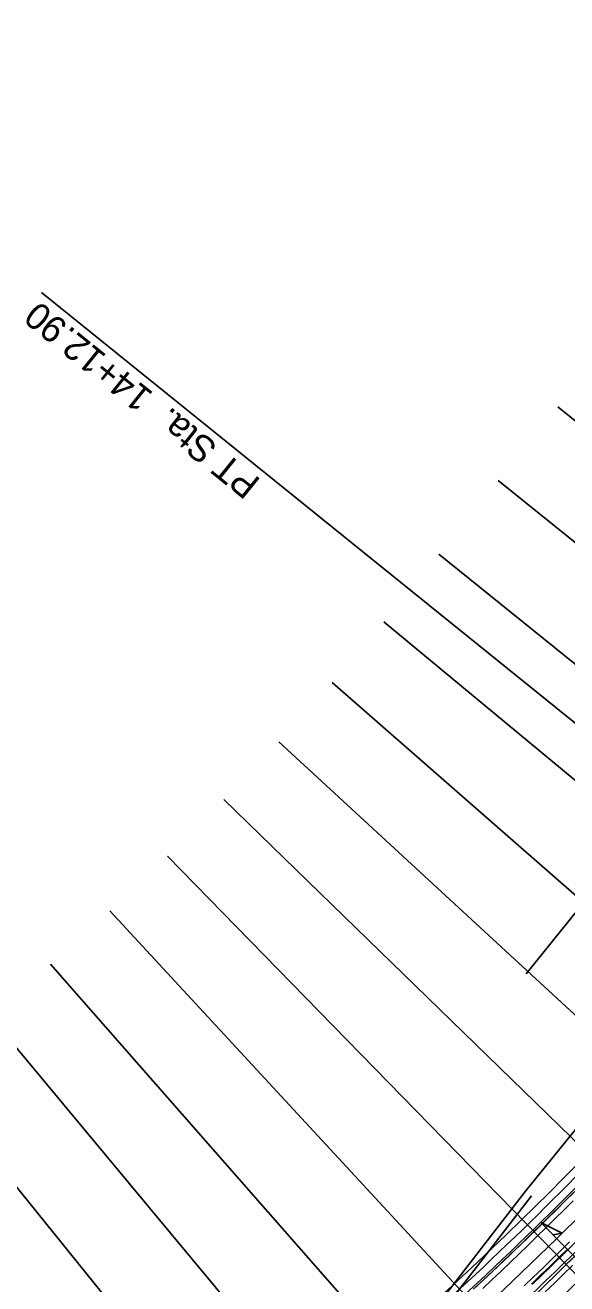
# Model space of a CAD drawing. Extents: x 2293233 to 2294507, y 892788 to 894229.
# Drawn here: x 2293544.7 to 2293687.7, y 893239.9 to 893572.2 of the extents above; entities that cross this region are included whole.
import ezdxf

# ---------------------------------------------------------------- set-up
doc = ezdxf.new("R2010")
doc.units = 0
for name, color, linetype in [('COGO Default Curve', 7, 'Continuous'), ('Prop EOT', 7, 'Continuous'), ('Prop Horizontal Alignment', 7, 'Continuous'), ('Prop Paved Shoulder', 7, 'Continuous'), ('Prop Superelevation  Arrow CELL', 7, 'Continuous'), ('Scratch_Level_0', 7, 'Continuous'), ('Scratch_Level_4', 7, 'Continuous'), ('Scratch_Level_5', 7, 'Continuous')]:
    doc.layers.add(name, color=color, linetype=linetype)

msp = doc.modelspace()

# ---------------------------------------------------------------- linework, layer by layer
at = {"layer": 'COGO Default Curve'}
for points in [[(2294044.74, 893680.7), (2293954.06, 893568.41), (2293770.67, 893341.16), (2293761.43, 893329.77), (2293756.77, 893324.11), (2293752.51, 893318.98), (2293748.22, 893313.88), (2293744.11, 893309.05), (2293739.98, 893304.26), (2293735.81, 893299.49), (2293731.62, 893294.74), (2293727.39, 893290.03), (2293722.91, 893285.09), (2293718.62, 893280.44), (2293714.3, 893275.81), (2293709.95, 893271.21), (2293705.56, 893266.64), (2293701.15, 893262.1), (2293696.71, 893257.59), (2293692.23, 893253.11), (2293687.73, 893248.66), (2293683.19, 893244.24), (2293678.63, 893239.85)], [(2293680.14, 893237.74), (2293686.34, 893243.78), (2293692.26, 893249.64), (2293698.14, 893255.55), (2293703.96, 893261.51), (2293709.74, 893267.51), (2293715.47, 893273.56), (2293720.92, 893279.42), (2293726.55, 893285.56), (2293732.12, 893291.75), (2293737.87, 893298.24), (2293743.8, 893305.01), (2293749.89, 893312.08), (2293756.38, 893319.69), (2293763.26, 893327.84), (2293770.53, 893336.54), (2293778.4, 893346.03), (2293786.88, 893356.32), (2293796.39, 893367.93), (2293808.61, 893382.91), (2293822.69, 893400.24), (2293860.23, 893446.62), (2293932.89, 893536.61), (2294046.75, 893677.72)], [(2293663.1, 893238.53), (2293667.97, 893243.08), (2293672.81, 893247.67), (2293677.62, 893252.29), (2293682.39, 893256.94), (2293687.14, 893261.63), (2293692.08, 893266.58)], [(2293689.56, 893264.05), (2293687.22, 893261.71), (2293684.86, 893259.37), (2293682.5, 893257.05), (2293680.13, 893254.73), (2293677.75, 893252.42), (2293675.37, 893250.11), (2293672.97, 893247.82), (2293670.57, 893245.53), (2293668.16, 893243.26), (2293665.75, 893240.99), (2293663.32, 893238.73)], [(2293689.37, 893261.8), (2293687.02, 893259.45), (2293684.66, 893257.11), (2293682.3, 893254.78), (2293679.92, 893252.46), (2293677.54, 893250.14), (2293675.15, 893247.84), (2293672.75, 893245.54), (2293670.35, 893243.25), (2293667.93, 893240.97), (2293665.51, 893238.7)], [(2293688.46, 893250.98), (2293686.07, 893248.64), (2293683.67, 893246.31), (2293681.26, 893243.99), (2293678.85, 893241.67), (2293676.42, 893239.37)], [(2293687.99, 893249.16), (2293685.6, 893246.82), (2293683.2, 893244.49), (2293680.79, 893242.16), (2293678.37, 893239.85)], [(2293682.27, 893239.81), (2293684.65, 893242.12), (2293687.02, 893244.44), (2293689.38, 893246.77)], [(2293682.03, 893237.81), (2293684.43, 893240.11), (2293686.81, 893242.42), (2293689.19, 893244.74)]]:
    msp.add_lwpolyline(points, dxfattribs=at)
for radius in [944, 956]:
    msp.add_arc((2293023.75, 893925.54), radius, 308.6085, 321.09608, dxfattribs=at)
at = {"layer": 'Prop EOT'}
for radius, start in [(938, 309.40221), (962, 308.6085)]:
    msp.add_arc((2293023.75, 893925.54), radius, start, 321.09608, dxfattribs=at)
at = {"layer": 'Prop Horizontal Alignment'}
for p, q in [((2293761.87, 893329.86), (2293549.03, 893501.62)), ((2293687.08, 893245.48), (2293683.59, 893249.05))]:
    msp.add_line(p, q, dxfattribs=at)
msp.add_arc((2293023.75, 893925.54), 950, 308.6085, 321.09608, dxfattribs=at)
msp.add_arc((2293023.75, 893925.54), 950, 308.6085, 321.09608, dxfattribs=at)
at = {"layer": 'Prop Paved Shoulder'}
for radius, start in [(936, 310.01837), (964, 308.6085)]:
    msp.add_arc((2293023.75, 893925.54), radius, start, 321.09608, dxfattribs=at)
at = {"layer": 'Prop Superelevation  Arrow CELL'}
msp.add_line((2293680.83, 893256.14), (2293697.64, 893239.02), dxfattribs=at)
msp.add_lwpolyline([(2293680.83, 893256.14), (2293686.46, 893253.26), (2293684.07, 893252.84)], close=True, dxfattribs=at)
at = {"layer": 'Scratch_Level_0'}
for p, q in [((2293696.14, 893345.54), (2293676.95, 893321.77)), ((2293678.41, 893263.12), (2293651.3, 893228.13))]:
    msp.add_line(p, q, dxfattribs=at)
at = {"layer": 'Scratch_Level_4'}
for p, q in [((2293685.31, 893471.45), (2293918.77, 893283.04)), ((2293669.61, 893451.99), (2293903.07, 893263.59)), ((2293653.9, 893432.54), (2293887.36, 893244.13)), ((2293639.43, 893414.71), (2293870.31, 893223.16)), ((2293625.77, 893398.69), (2293851.53, 893201.12)), ((2293611.7, 893383.03), (2293832.18, 893179.59)), ((2293597.22, 893367.75), (2293812.28, 893158.58)), ((2293582.35, 893352.85), (2293791.82, 893138.1)), ((2293567.08, 893338.35), (2293770.84, 893118.16)), ((2293551.45, 893324.26), (2293749.33, 893098.78)), ((2293535.44, 893310.58), (2293727.33, 893079.98)), ((2293517.66, 893296.15), (2293706.3, 893062.88))]:
    msp.add_line(p, q, dxfattribs=at)
at = {"layer": 'Scratch_Level_5'}
for p, q in [((2293676.84, 893264.33), (2293818.17, 893439.42)), ((2293648.21, 893227.37), (2293676.84, 893264.33))]:
    msp.add_line(p, q, dxfattribs=at)
msp.add_arc((2293023.75, 893925.54), 934, 310.67386, 321.09608, dxfattribs=at)

# ---------------------------------------------------------------- texts
at = {"layer": 'Prop Horizontal Alignment'}
msp.add_text('PT Sta.  14+12.90', height=7, rotation=141.0961, dxfattribs=at).set_placement((2293607.21, 893452.1))

doc.saveas('drawing.dxf')
